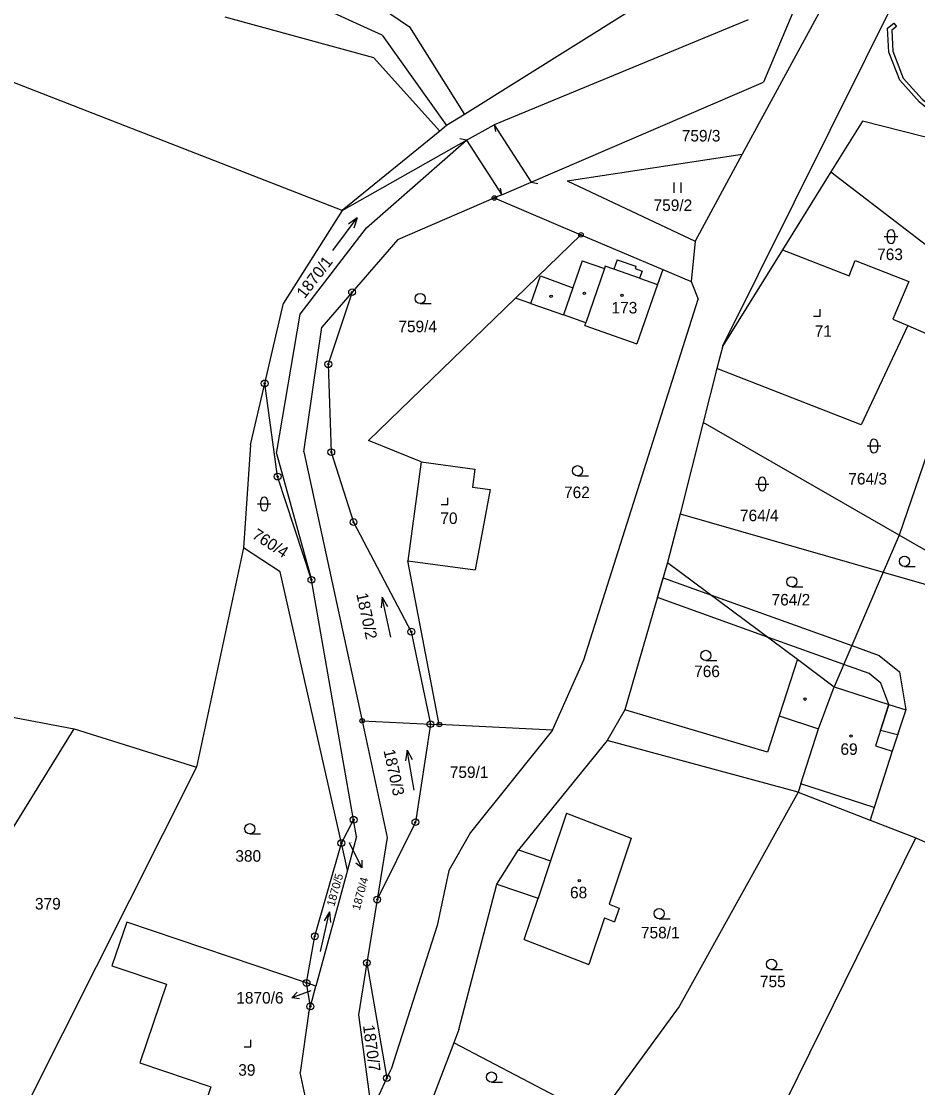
# Model space of a CAD drawing. Extents: x -546762 to -540209, y -1046851 to -1035694.
# Drawn here: x -544158.4 to -544026.5, y -1042231.6 to -1042074.7 of the extents above; entities that cross this region are included whole.
import ezdxf

# ---------------------------------------------------------------- set-up
doc = ezdxf.new("R2010")
doc.units = 0
for name, color, linetype in [('Vrstva 1', 7, 'Continuous'), ('Vrstva 16', 7, 'Continuous'), ('Vrstva 18', 7, 'Continuous'), ('Vrstva 19', 7, 'Continuous'), ('Vrstva 24', 7, 'Continuous'), ('Vrstva 25', 7, 'Continuous'), ('Vrstva 26', 7, 'Continuous'), ('Vrstva 3', 7, 'Continuous'), ('Vrstva 30', 7, 'Continuous'), ('Vrstva 37', 7, 'Continuous'), ('Vrstva 4', 7, 'Continuous'), ('Vrstva 6', 7, 'Continuous')]:
    doc.layers.add(name, color=color, linetype=linetype)

msp = doc.modelspace()

# ---------------------------------------------------------------- linework, layer by layer
at = {"layer": 'Vrstva 1'}
for p, q in [((-544103, -1042106.79), (-544109.71, -1042114.54)), ((-544109.71, -1042114.54), (-544114.15, -1042119.68)), ((-544109.71, -1042114.54), (-544113.22, -1042125.14)), ((-544122.58, -1042127.97), (-544119.81, -1042116.14)), ((-544113.22, -1042125.14), (-544112.78, -1042138.08)), ((-544124.69, -1042137.01), (-544122.58, -1042127.97)), ((-544120.68, -1042141.67), (-544122.58, -1042127.97)), ((-544112.78, -1042138.08), (-544109.51, -1042148.36)), ((-544115.7, -1042156.86), (-544120.68, -1042141.67)), ((-544109.51, -1042148.36), (-544101, -1042164.5)), ((-544111.29, -1042195.6), (-544120.29, -1042155.68)), ((-544109.49, -1042192.17), (-544115.7, -1042156.86)), ((-544101, -1042164.5), (-544098.18, -1042178.1)), ((-544108.24, -1042177.62), (-544098.18, -1042178.1)), ((-544098.18, -1042178.1), (-544100.39, -1042192.52)), ((-544098.18, -1042178.1), (-544096.88, -1042178.16)), ((-544111.29, -1042195.6), (-544109.49, -1042192.17)), ((-544109.05, -1042194.65), (-544109.49, -1042192.17)), ((-544100.39, -1042192.52), (-544106.02, -1042203.91)), ((-544104.53, -1042194.76), (-544106.02, -1042203.91)), ((-544115.2, -1042209.31), (-544111.29, -1042195.6)), ((-544110.39, -1042199.57), (-544111.29, -1042195.6)), ((-544106.02, -1042203.91), (-544107.54, -1042213.22)), ((-544116.42, -1042216.18), (-544142.9, -1042207.22)), ((-544116.42, -1042216.18), (-544115.2, -1042209.31)), ((-544107.54, -1042213.22), (-544108.78, -1042220.85)), ((-544107.54, -1042213.22), (-544104.6, -1042230.19)), ((-544115.05, -1042216.65), (-544116.42, -1042216.18)), ((-544115.86, -1042219.62), (-544116.42, -1042216.18)), ((-544115.86, -1042219.62), (-544115.05, -1042216.65)), ((-544116.15, -1042220.7), (-544115.86, -1042219.62)), ((-544104.6, -1042230.19), (-544103.97, -1042228.84)), ((-544106.86, -1042235.08), (-544104.6, -1042230.19))]:
    msp.add_line(p, q, dxfattribs=at)
for points in [[(-544022.33, -1042019.89), (-544049.15, -1042083.64)], [(-544027.37, -1042048.39), (-544052.28, -1042094.25)], [(-544105.28, -1042076.73), (-544126, -1042067.28)], [(-544112.11, -1042068.08), (-544101.27, -1042075.52)], [(-544055.15, -1042122.43), (-544028.83, -1042069.57)], [(-544128.46, -1042074.02), (-544106.54, -1042080.01)], [(-544068.77, -1042073.13), (-544093.16, -1042088.38)], [(-544051.43, -1042074.46), (-544088.8, -1042089.94)], [(-544101.27, -1042075.52), (-544093.16, -1042088.38)], [(-544105.28, -1042076.73), (-544095.8, -1042090.03)], [(-544106.54, -1042080.01), (-544096.79, -1042090.83)], [(-544083.35, -1042098.35), (-544049.15, -1042083.64)], [(-544093.16, -1042088.38), (-544095.8, -1042090.03)], [(-544095.8, -1042090.03), (-544096.79, -1042090.83)], [(-544092.89, -1042092.18), (-544088.8, -1042089.94)], [(-544034.58, -1042089.36), (-544039.23, -1042096.84)], [(-544022.79, -1042092.37), (-544034.58, -1042089.36)], [(-544096.79, -1042090.83), (-544111.17, -1042102.5)], [(-544111.17, -1042102.5), (-544092.89, -1042092.18)], [(-544107.57, -1042105.06), (-544092.89, -1042092.18)], [(-544078.03, -1042098.14), (-544052.28, -1042094.25)], [(-544052.28, -1042094.25), (-544059.23, -1042107.05)], [(-544039.23, -1042096.84), (-544046.37, -1042108.31)], [(-544039.23, -1042096.84), (-544015.68, -1042114.87)], [(-544087.68, -1042100.21), (-544083.35, -1042098.35)], [(-544078.03, -1042098.14), (-544059.23, -1042107.05)], [(-544103, -1042106.79), (-544088.78, -1042100.68)], [(-544087.68, -1042100.21), (-544088.78, -1042100.68)], [(-544088.78, -1042100.68), (-544076.02, -1042106.1)], [(-544111.17, -1042102.5), (-544119.81, -1042116.14)], [(-544117.36, -1042117.77), (-544107.57, -1042105.06)], [(-544076.02, -1042106.1), (-544085.64, -1042115.42)], [(-544076.02, -1042106.1), (-544063.97, -1042111.21)], [(-544059.23, -1042107.05), (-544059.81, -1042112.98)], [(-544046.37, -1042108.31), (-544055.15, -1042122.43)], [(-544046.37, -1042108.31), (-544036.55, -1042112.16)], [(-544036.55, -1042112.16), (-544035.65, -1042109.88)], [(-544035.65, -1042109.88), (-544027.74, -1042112.98)], [(-544063.97, -1042111.21), (-544064.74, -1042113.4)], [(-544063.97, -1042111.21), (-544059.81, -1042112.98)], [(-544064.74, -1042113.4), (-544067.8, -1042122.12)], [(-544059.81, -1042112.98), (-544058.79, -1042115.59)], [(-544027.74, -1042112.98), (-544030.1, -1042118.5)], [(-544085.64, -1042115.42), (-544107.3, -1042136.38)], [(-544083.41, -1042116.2), (-544085.64, -1042115.42)], [(-544083.41, -1042116.2), (-544078.6, -1042117.89)], [(-544075.62, -1042168.64), (-544058.79, -1042115.59)], [(-544120.85, -1042138.3), (-544117.36, -1042117.77)], [(-544075.3, -1042119.05), (-544078.6, -1042117.89)], [(-544116.82, -1042138.01), (-544114.15, -1042119.68)], [(-544075.43, -1042119.44), (-544075.3, -1042119.05)], [(-544075.43, -1042119.44), (-544067.8, -1042122.12)], [(-544027.89, -1042119.44), (-544034.77, -1042134.07)], [(-544030.1, -1042118.5), (-544027.89, -1042119.44)], [(-544027.89, -1042119.44), (-544019.79, -1042122.99)], [(-544055.15, -1042122.43), (-544056, -1042125.75)], [(-544019.79, -1042122.99), (-544029.19, -1042150.29)], [(-544056, -1042125.75), (-544058.02, -1042133.7)], [(-544034.77, -1042134.07), (-544056, -1042125.75)], [(-544058.02, -1042133.7), (-544061.44, -1042147.14)], [(-544029.19, -1042150.29), (-544058.02, -1042133.7)], [(-544124.69, -1042137.01), (-544125.7, -1042152.16)], [(-544099.56, -1042139.52), (-544107.3, -1042136.38)], [(-544120.85, -1042138.3), (-544115.7, -1042156.86)], [(-544116.82, -1042138.01), (-544108.24, -1042177.62)], [(-544099.56, -1042139.52), (-544101.5, -1042154.09)], [(-544099.56, -1042139.52), (-544091.63, -1042140.57)], [(-544091.63, -1042140.57), (-544091.98, -1042143.25)], [(-544091.98, -1042143.25), (-544089.41, -1042143.59)], [(-544089.41, -1042143.59), (-544091.59, -1042155.4)], [(-544061.44, -1042147.14), (-544063.26, -1042154.31)], [(-544061.44, -1042147.14), (-544031.52, -1042155.74)], [(-544029.19, -1042150.29), (-544031.52, -1042155.74)], [(-544007.95, -1042162.51), (-544029.19, -1042150.29)], [(-544125.7, -1042152.16), (-544132.62, -1042184.45)], [(-544120.29, -1042155.68), (-544125.7, -1042152.16)], [(-544096.88, -1042178.16), (-544101.5, -1042154.09)], [(-544101.5, -1042154.09), (-544091.59, -1042155.4)], [(-544063.26, -1042154.31), (-544069.56, -1042175.98)], [(-544063.26, -1042154.31), (-544044.14, -1042168.56)], [(-544031.52, -1042155.74), (-544038.73, -1042172.59)], [(-544031.52, -1042155.74), (-544007.95, -1042162.51)], [(-544080.19, -1042178.96), (-544075.62, -1042168.64)], [(-544044.14, -1042168.56), (-544046.85, -1042176.89)], [(-544044.14, -1042168.56), (-544038.73, -1042172.59)], [(-544186.87, -1042171.92), (-544150.62, -1042178.77)], [(-544038.73, -1042172.59), (-544030.68, -1042175.2)], [(-544069.56, -1042175.98), (-544072.14, -1042180.49)], [(-544048.58, -1042182.24), (-544069.56, -1042175.98)], [(-544030.68, -1042175.2), (-544028.21, -1042176)], [(-544028.21, -1042176), (-544030.19, -1042182.09)], [(-544108.24, -1042177.62), (-544104.53, -1042194.76)], [(-544046.85, -1042176.89), (-544048.58, -1042182.24)], [(-544176.25, -1042220.24), (-544150.62, -1042178.77)], [(-544150.62, -1042178.77), (-544132.62, -1042184.45)], [(-544080.19, -1042178.96), (-544096.88, -1042178.16)], [(-544080.19, -1042178.96), (-544092.27, -1042194.03)], [(-544072.14, -1042180.49), (-544085.23, -1042196.6)], [(-544044.07, -1042188.1), (-544072.14, -1042180.49)], [(-544030.19, -1042182.09), (-544032.87, -1042190.36)], [(-544132.62, -1042184.45), (-544157.25, -1042233.4)], [(-544044.07, -1042188.1), (-544061.54, -1042219.66)], [(-544044.07, -1042188.1), (-544033.47, -1042192.21)], [(-544032.87, -1042190.36), (-544033.47, -1042192.21)], [(-544078.14, -1042191.18), (-544080.49, -1042198.19)], [(-544078.14, -1042191.18), (-544068.63, -1042194.88)], [(-544033.47, -1042192.21), (-544026.72, -1042194.83)], [(-544109.05, -1042194.65), (-544110.39, -1042199.57)], [(-544092.27, -1042194.03), (-544095.45, -1042199.65)], [(-544068.63, -1042194.88), (-544071.89, -1042204.6)], [(-544052.74, -1042247.55), (-544026.72, -1042194.83)], [(-544026.72, -1042194.83), (-544012.05, -1042201.4)], [(-544088.41, -1042201.65), (-544085.23, -1042196.6)], [(-544085.23, -1042196.6), (-544080.49, -1042198.19)], [(-544110.39, -1042199.57), (-544115.05, -1042216.65)], [(-544095.45, -1042199.65), (-544097.17, -1042207.74)], [(-544093.98, -1042223.01), (-544088.41, -1042201.65)], [(-544088.41, -1042201.65), (-544082.34, -1042203.69)], [(-544084.38, -1042209.76), (-544082.34, -1042203.69)], [(-544071.89, -1042204.6), (-544070.4, -1042205.18)], [(-544070.4, -1042205.18), (-544071.07, -1042207.16)], [(-544142.9, -1042207.22), (-544145.08, -1042213.66)], [(-544097.17, -1042207.74), (-544103.97, -1042228.84)], [(-544072.56, -1042206.58), (-544074.87, -1042213.46)], [(-544072.56, -1042206.58), (-544071.07, -1042207.16)], [(-544084.38, -1042209.76), (-544074.87, -1042213.46)], [(-544145.08, -1042213.66), (-544137.02, -1042216.38)], [(-544137.02, -1042216.38), (-544140.94, -1042227.94)], [(-544061.54, -1042219.66), (-544071.69, -1042233.46)], [(-544116.15, -1042220.7), (-544117.38, -1042229.36)], [(-544108.78, -1042220.85), (-544106.86, -1042235.08)], [(-544093.98, -1042223.01), (-544094.75, -1042225.01)], [(-544094.75, -1042225.01), (-544098.98, -1042236.04)], [(-544079.59, -1042232.93), (-544094.75, -1042225.01)], [(-544140.94, -1042227.94), (-544130.52, -1042231.47)], [(-544115.73, -1042236.89), (-544117.38, -1042229.36)], [(-544130.52, -1042231.47), (-544132.14, -1042236.25)]]:
    msp.add_lwpolyline(points, dxfattribs=at)
at = {"layer": 'Vrstva 16'}
for p, q in [((-544109.63, -1042196.56), (-544108.29, -1042199.24)), ((-544115.77, -1042217.32), (-544118.58, -1042218.37))]:
    msp.add_line(p, q, dxfattribs=at)
for points in [[(-544110.15, -1042195.52), (-544109.63, -1042196.56)], [(-544108.29, -1042198.13), (-544108.29, -1042199.24), (-544109.18, -1042198.57)], [(-544117.47, -1042218.49), (-544118.58, -1042218.37), (-544117.82, -1042217.55)]]:
    msp.add_lwpolyline(points, dxfattribs=at)
at = {"layer": 'Vrstva 24'}
for centre, radius in [((-544088.78, -1042100.68), 0.335), ((-544088.78, -1042100.68), 0.067), ((-544076.02, -1042106.1), 0.335), ((-544076.02, -1042106.1), 0.067), ((-544109.71, -1042114.54), 0.5), ((-544109.71, -1042114.54), 0.1), ((-544113.22, -1042125.14), 0.5), ((-544113.22, -1042125.14), 0.1), ((-544122.58, -1042127.97), 0.5), ((-544122.58, -1042127.97), 0.1), ((-544112.78, -1042138.08), 0.5), ((-544112.78, -1042138.08), 0.1), ((-544120.68, -1042141.67), 0.5), ((-544120.68, -1042141.67), 0.1), ((-544109.51, -1042148.36), 0.5), ((-544109.51, -1042148.36), 0.1), ((-544115.7, -1042156.86), 0.5), ((-544115.7, -1042156.86), 0.1), ((-544101, -1042164.5), 0.5), ((-544101, -1042164.5), 0.1), ((-544108.24, -1042177.62), 0.335), ((-544108.24, -1042177.62), 0.067), ((-544098.18, -1042178.1), 0.5), ((-544098.18, -1042178.1), 0.1), ((-544096.88, -1042178.16), 0.335), ((-544096.88, -1042178.16), 0.067), ((-544109.49, -1042192.17), 0.5), ((-544109.49, -1042192.17), 0.1), ((-544100.39, -1042192.52), 0.5), ((-544100.39, -1042192.52), 0.1), ((-544111.29, -1042195.6), 0.5), ((-544111.29, -1042195.6), 0.1), ((-544106.02, -1042203.91), 0.5), ((-544106.02, -1042203.91), 0.1), ((-544115.2, -1042209.31), 0.5), ((-544115.2, -1042209.31), 0.1), ((-544107.54, -1042213.22), 0.5), ((-544107.54, -1042213.22), 0.1), ((-544116.42, -1042216.18), 0.5), ((-544116.42, -1042216.18), 0.1), ((-544115.86, -1042219.62), 0.5), ((-544115.86, -1042219.62), 0.1), ((-544104.6, -1042230.19), 0.5), ((-544104.6, -1042230.19), 0.1)]:
    msp.add_circle(centre, radius, dxfattribs=at)
at = {"layer": 'Vrstva 25'}
for p, q in [((-544062.28, -1042099.91), (-544062.28, -1042098.41)), ((-544061.28, -1042099.91), (-544061.28, -1042098.41)), ((-544030.87, -1042106.87), (-544030.87, -1042105.87)), ((-544029.87, -1042105.87), (-544029.87, -1042106.87)), ((-544031.37, -1042106.37), (-544029.37, -1042106.37)), ((-544099.69, -1042116.22), (-544098.09, -1042116.22)), ((-544033.89, -1042137.17), (-544031.89, -1042137.17)), ((-544033.39, -1042137.67), (-544033.39, -1042136.67)), ((-544032.39, -1042136.67), (-544032.39, -1042137.67)), ((-544076.53, -1042141.56), (-544074.93, -1042141.56)), ((-544050.34, -1042142.77), (-544048.34, -1042142.77)), ((-544049.84, -1042143.27), (-544049.84, -1042142.27)), ((-544048.84, -1042142.27), (-544048.84, -1042143.27)), ((-544123.66, -1042145.69), (-544121.66, -1042145.69)), ((-544123.16, -1042146.19), (-544123.16, -1042145.19)), ((-544122.16, -1042145.19), (-544122.16, -1042146.19)), ((-544028.4, -1042154.89), (-544026.8, -1042154.89)), ((-544044.98, -1042157.9), (-544043.38, -1042157.9)), ((-544057.63, -1042168.73), (-544056.03, -1042168.73)), ((-544124.78, -1042194.24), (-544123.18, -1042194.24)), ((-544064.51, -1042206.73), (-544062.91, -1042206.73)), ((-544047.96, -1042214.18), (-544046.36, -1042214.18)), ((-544089.19, -1042230.77), (-544087.59, -1042230.77))]:
    msp.add_line(p, q, dxfattribs=at)
for points in [[(-544112.53, -1042108.43), (-544108.97, -1042103.59), (-544110.26, -1042104.51)], [(-544108.97, -1042103.59), (-544109.46, -1042105.1)], [(-544041.8, -1042118.05), (-544040.8, -1042118.05), (-544040.8, -1042117.05)], [(-544096.6, -1042145.8), (-544095.6, -1042145.8), (-544095.6, -1042144.8)], [(-544103.99, -1042165.29), (-544105.29, -1042159.43), (-544105.45, -1042161)], [(-544105.29, -1042159.43), (-544104.48, -1042160.79)], [(-544100.59, -1042187.82), (-544101.63, -1042181.92), (-544101.86, -1042183.48)], [(-544101.63, -1042181.92), (-544100.88, -1042183.31)], [(-544114.36, -1042211.55), (-544113.02, -1042205.71), (-544113.84, -1042207.06)], [(-544113.02, -1042205.71), (-544112.87, -1042207.28)], [(-544125.62, -1042225.56), (-544124.62, -1042225.56), (-544124.62, -1042224.56)]]:
    msp.add_lwpolyline(points, dxfattribs=at)
for centre, radius in [((-544099.69, -1042115.47), 0.75), ((-544080.41, -1042115.17), 0.175), ((-544075.52, -1042114.69), 0.175), ((-544069.96, -1042114.99), 0.175), ((-544076.53, -1042140.81), 0.75), ((-544028.4, -1042154.14), 0.75), ((-544044.98, -1042157.15), 0.75), ((-544057.63, -1042167.98), 0.75), ((-544043.02, -1042174.42), 0.175), ((-544036.26, -1042179.86), 0.175), ((-544124.78, -1042193.49), 0.75), ((-544076.27, -1042201.12), 0.175), ((-544064.51, -1042205.98), 0.75), ((-544047.96, -1042213.43), 0.75), ((-544089.19, -1042230.02), 0.75)]:
    msp.add_circle(centre, radius, dxfattribs=at)
for centre, start, end in [((-544030.37, -1042105.87), 0, 180), ((-544030.37, -1042106.87), 180, 0), ((-544032.89, -1042136.67), 0, 180), ((-544032.89, -1042137.67), 180, 0), ((-544049.34, -1042142.27), 0, 180), ((-544049.34, -1042143.27), 180, 0), ((-544122.66, -1042145.19), 0, 180), ((-544122.66, -1042146.19), 180, 0)]:
    msp.add_arc(centre, 0.5, start, end, dxfattribs=at)
at = {"layer": 'Vrstva 26'}
for p, q in [((-544088.8, -1042089.94), (-544088.59, -1042090.92)), ((-544092.89, -1042092.18), (-544093.87, -1042091.97)), ((-544087.68, -1042100.21), (-544087.89, -1042099.23)), ((-544083.35, -1042098.35), (-544082.37, -1042098.56))]:
    msp.add_line(p, q, dxfattribs=at)
at = {"layer": 'Vrstva 3'}
for points in [[(-544072.55, -1042111.06), (-544075.3, -1042119.05)], [(-544072.44, -1042110.73), (-544072.55, -1042111.06)], [(-544071.16, -1042111.17), (-544072.44, -1042110.73)], [(-544067.38, -1042112.48), (-544071.16, -1042111.17)], [(-544064.74, -1042113.4), (-544067.8, -1042122.12)], [(-544067.38, -1042112.48), (-544064.74, -1042113.4)], [(-544075.43, -1042119.44), (-544075.3, -1042119.05)], [(-544075.43, -1042119.44), (-544067.8, -1042122.12)], [(-544041.05, -1042178.77), (-544038.73, -1042172.59)], [(-544038.73, -1042172.59), (-544030.68, -1042175.2)], [(-544030.68, -1042175.2), (-544032.66, -1042181.29)], [(-544043.67, -1042186.86), (-544041.05, -1042178.77)], [(-544030.19, -1042182.09), (-544032.87, -1042190.36)], [(-544032.66, -1042181.29), (-544030.19, -1042182.09)], [(-544032.87, -1042190.36), (-544043.67, -1042186.86)], [(-544078.14, -1042191.18), (-544080.49, -1042198.19)], [(-544078.14, -1042191.18), (-544068.63, -1042194.88)], [(-544068.63, -1042194.88), (-544071.89, -1042204.6)], [(-544080.49, -1042198.19), (-544082.34, -1042203.69)], [(-544084.38, -1042209.76), (-544082.34, -1042203.69)], [(-544071.89, -1042204.6), (-544070.4, -1042205.18)], [(-544070.4, -1042205.18), (-544071.07, -1042207.16)], [(-544072.56, -1042206.58), (-544074.87, -1042213.46)], [(-544072.56, -1042206.58), (-544071.07, -1042207.16)], [(-544084.38, -1042209.76), (-544074.87, -1042213.46)]]:
    msp.add_lwpolyline(points, dxfattribs=at)
at = {"layer": 'Vrstva 30'}
for points in [[(-544015.4, -1042095.16), (-544017.15, -1042093.95), (-544020.81, -1042090.97), (-544026.2, -1042086.59), (-544029.1, -1042083.36), (-544030.71, -1042079.21), (-544030.87, -1042075.71), (-544029.97, -1042074.98), (-544029.59, -1042075.44), (-544030.25, -1042075.99), (-544030.11, -1042079.09), (-544028.58, -1042083.04), (-544025.78, -1042086.15), (-544020.56, -1042090.4), (-544016.79, -1042093.47), (-544015.08, -1042094.66), (-544004.85, -1042100.77), (-544005.64, -1042103.47)], [(-544032.1, -1042167.99), (-544029.14, -1042170.42), (-544028.21, -1042176), (-544029.41, -1042179.68), (-544031.93, -1042179.05), (-544030.68, -1042175.2), (-544031.88, -1042172.06), (-544033.6, -1042170.63), (-544037.32, -1042169.3), (-544048.55, -1042165.28), (-544064.76, -1042159.46), (-544063.92, -1042156.58), (-544056.79, -1042159.13), (-544036.14, -1042166.54), (-544032.1, -1042167.99)]]:
    msp.add_lwpolyline(points, dxfattribs=at)
at = {"layer": 'Vrstva 37'}
for centre in [(-544069.96, -1042114.99), (-544036.26, -1042179.86), (-544076.27, -1042201.12)]:
    msp.add_circle(centre, 0.175, dxfattribs=at)
at = {"layer": 'Vrstva 4'}
for points in [[(-544088.8, -1042089.94), (-544083.35, -1042098.35)], [(-544092.89, -1042092.18), (-544087.68, -1042100.21)], [(-544075.82, -1042109.94), (-544077.2, -1042113.9)], [(-544075.82, -1042109.94), (-544072.55, -1042111.06)], [(-544070.67, -1042109.76), (-544071.16, -1042111.17)], [(-544070.67, -1042109.76), (-544067.93, -1042110.71)], [(-544083.41, -1042116.2), (-544081.97, -1042112.14)], [(-544081.97, -1042112.14), (-544077.2, -1042113.9)], [(-544072.55, -1042111.06), (-544075.3, -1042119.05)], [(-544072.44, -1042110.73), (-544072.55, -1042111.06)], [(-544071.16, -1042111.17), (-544072.44, -1042110.73)], [(-544067.38, -1042112.48), (-544071.16, -1042111.17)], [(-544067.93, -1042110.71), (-544068.06, -1042111.08)], [(-544068.06, -1042111.08), (-544067.02, -1042111.44)], [(-544067.02, -1042111.44), (-544067.38, -1042112.48)], [(-544067.38, -1042112.48), (-544064.74, -1042113.4)], [(-544077.2, -1042113.9), (-544078.6, -1042117.89)], [(-544041.05, -1042178.77), (-544038.73, -1042172.59)], [(-544030.68, -1042175.2), (-544032.66, -1042181.29)], [(-544046.85, -1042176.89), (-544041.05, -1042178.77)], [(-544043.67, -1042186.86), (-544041.05, -1042178.77)], [(-544032.66, -1042181.29), (-544030.19, -1042182.09)], [(-544043.67, -1042186.86), (-544044.07, -1042188.1)], [(-544032.87, -1042190.36), (-544043.67, -1042186.86)], [(-544080.49, -1042198.19), (-544082.34, -1042203.69)]]:
    msp.add_lwpolyline(points, dxfattribs=at)
at = {"layer": 'Vrstva 6'}
msp.add_lwpolyline([(-544111.17, -1042102.5), (-544173.19, -1042078.38)], dxfattribs=at)

# ---------------------------------------------------------------- texts
at = {"layer": 'Vrstva 16'}
msp.add_text('1870/4', height=1.2, rotation=74.7392, dxfattribs=at).set_placement((-544108.59, -1042205.56))
msp.add_text('1870/6', height=1.7, dxfattribs=at).set_placement((-544126.76, -1042219.21))
at = {"layer": 'Vrstva 18'}
for s, height, p in [('759/3', 1.7, (-544061.18, -1042092.37)), ('759/2', 1.7, (-544065.33, -1042102.6)), ('763', 1.7, (-544032.42, -1042109.82)), ('759/4', 1.7, (-544102.9, -1042120.43)), ('764/3', 1.7, (-544036.66, -1042142.84)), ('762', 1.7, (-544078.51, -1042144.84)), ('764/4', 1.7, (-544052.61, -1042148.24)), ('764/2', 1.7, (-544047.96, -1042160.64)), ('766', 1.7, (-544059.36, -1042171.18)), ('759/1', 1.7, (-544095.33, -1042186.01)), ('380', 1.7, (-544126.9, -1042198.34)), ('1870/4', 0.1, (-544110.15, -1042195.52)), ('379', 1.7, (-544156.4, -1042205.37)), ('758/1', 1.7, (-544067.19, -1042209.62)), ('755', 1.7, (-544049.67, -1042216.8)), ('1870/6', 0.1, (-544115.77, -1042217.32))]:
    msp.add_text(s, height=height, dxfattribs=at).set_placement(p)
for s, height, rotation, p in [('1870/1', 1.7, 52.3944, (-544116.7, -1042115.59)), ('760/4', 1.7, 326.9501, (-544124.58, -1042150.63)), ('1870/2', 1.7, 282.2221, (-544109.11, -1042158.96)), ('1870/3', 1.7, 282.2221, (-544105.1, -1042181.98)), ('1870/5', 1.2, 74.057, (-544112.34, -1042205.01)), ('1870/7', 1.7, 277.6843, (-544108.12, -1042222.44))]:
    msp.add_text(s, height=height, rotation=rotation, dxfattribs=at).set_placement(p)
at = {"layer": 'Vrstva 19'}
for s, p in [('173', (-544071.52, -1042117.67)), ('71', (-544041.61, -1042121.11)), ('70', (-544096.72, -1042148.65)), ('69', (-544037.82, -1042182.62)), ('68', (-544077.63, -1042203.72)), ('39', (-544126.47, -1042229.83))]:
    msp.add_text(s, height=1.7, dxfattribs=at).set_placement(p)

doc.saveas('drawing.dxf')
